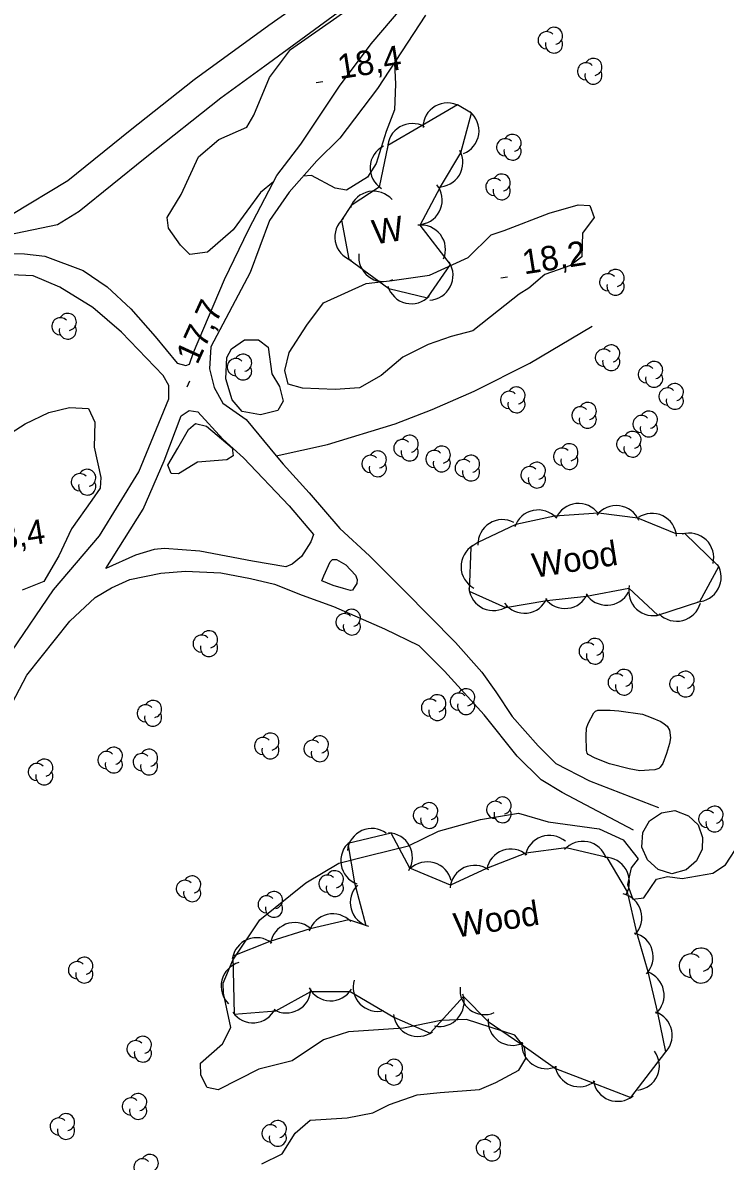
# Model space of a CAD drawing. Extents: x 646142 to 649934, y 5874075 to 5876351.
# Drawn here: x 646701.5 to 646787.3, y 5874932.5 to 5875071.6 of the extents above; entities that cross this region are included whole.
import ezdxf

# ---------------------------------------------------------------- set-up
doc = ezdxf.new("R2010")
doc.units = 0
for name, color, linetype in [('Niveau 2', 7, 'Continuous'), ('Niveau 21', 7, 'Continuous'), ('Niveau 22', 7, 'Continuous'), ('Niveau 3', 7, 'Continuous'), ('Niveau 31', 7, 'Continuous'), ('Niveau 44', 7, 'Continuous')]:
    doc.layers.add(name, color=color, linetype=linetype)

msp = doc.modelspace()

# ---------------------------------------------------------------- linework, layer by layer
at = {"layer": 'Niveau 2'}
for points in [[(646732.14, 5875052.16), (646730.58, 5875050.87), (646727.24, 5875046.31), (646724.1, 5875043.57), (646721.92, 5875043.29), (646720.79, 5875044.42), (646719.34, 5875046.52), (646719.17, 5875047.79), (646720.86, 5875050.6), (646722.97, 5875055.24), (646725.46, 5875057.35), (646728.88, 5875058.83), (646729.74, 5875060.3), (646731.68, 5875064.93), (646734.24, 5875068.32), (646739.89, 5875072.3), (646744.76, 5875075.81), (646746.72, 5875077.72)], [(646746.94, 5875066.77), (646746.91, 5875066.67), (646747.06, 5875064.12), (646746.91, 5875060.96), (646745.91, 5875058.33), (646744.67, 5875054.39), (646743.65, 5875052.74), (646741.06, 5875051.15), (646739.7, 5875051.39), (646736.79, 5875052.92), (646735.79, 5875052.86)], [(646762.17, 5875038.44), (646759.61, 5875036.44), (646756.51, 5875033.94), (646753.84, 5875033.27), (646751.02, 5875032.3), (646747.96, 5875030.73), (646745.3, 5875028.49), (646742.64, 5875027), (646739.7, 5875026.78), (646735.69, 5875026.94), (646733.96, 5875027.44), (646733.54, 5875029.1), (646734.05, 5875031.29), (646736.21, 5875034.66), (646738.25, 5875037.37), (646743.45, 5875039.75), (646746.66, 5875040.11), (646751.19, 5875040.75), (646755.94, 5875042.91), (646758.73, 5875045.69), (646760.31, 5875046.21), (646765.81, 5875048.32), (646769.38, 5875049.35), (646770.78, 5875049.28), (646771.31, 5875047.81), (646769.9, 5875045.9), (646769.79, 5875042.98), (646768.43, 5875041.95), (646765.27, 5875040.83), (646763.32, 5875039.17), (646762.17, 5875038.44)], [(646731.5, 5875031.97), (646731.95, 5875028.69), (646732.89, 5875027.13), (646733.32, 5875025.36), (646732.67, 5875024.2), (646730.56, 5875023.69), (646728.32, 5875024.1), (646727.1, 5875025.52), (646726.31, 5875028.08), (646726.44, 5875030.71), (646727, 5875031.74), (646728.59, 5875032.85), (646730.33, 5875032.87), (646731.5, 5875031.97)], [(646698.5, 5875020.48), (646701.81, 5875022.6), (646704.71, 5875023.99), (646707.22, 5875024.59), (646709.55, 5875024.47), (646710.33, 5875022.79), (646710.23, 5875019.75), (646711.06, 5875016.03), (646710.99, 5875014.74), (646709.95, 5875013.27), (646707.46, 5875009.76), (646705.93, 5875006.44), (646704.1, 5875003.33), (646701.46, 5875002.25)], [(646723.95, 5875022.31), (646727.12, 5875019.65), (646727.21, 5875018.66), (646726.43, 5875018.2), (646722.86, 5875017.92), (646720.54, 5875016.46), (646719.67, 5875016.51), (646719.23, 5875017.53), (646720.46, 5875019.6), (646721.77, 5875021.91), (646722.64, 5875022.62), (646723.95, 5875022.31)], [(646785.81, 5874967.65), (646787.37, 5874968.68), (646789.12, 5874971.38), (646791.44, 5874976.33), (646792.63, 5874983.01), (646794.26, 5874989.25), (646795.31, 5874992.65), (646795.9, 5874994.04), (646796.07, 5874994.05)], [(646761.63, 5874947.87), (646755.72, 5874949.8), (646752.59, 5874949.68), (646748.02, 5874948.74), (646741.32, 5874948.28), (646738.27, 5874947.29), (646734.41, 5874944.72), (646730.37, 5874943.71), (646725.41, 5874941.17), (646724.04, 5874941.47), (646723.28, 5874942.98), (646723.22, 5874944.44), (646725.93, 5874946.8), (646726.93, 5874948.8), (646726.06, 5874952.99), (646726.01, 5874954.21), (646727.18, 5874957.04), (646730.49, 5874961.96), (646736.1, 5874966.48), (646740.14, 5874968.89), (646743.84, 5874969.81), (646748.62, 5874971), (646752.31, 5874972.8), (646757.42, 5874974.24), (646762.06, 5874975), (646765.69, 5874973.94), (646771.91, 5874973.08), (646774.87, 5874971.74), (646776.68, 5874969.43), (646775.85, 5874968.32), (646775.38, 5874966.3), (646776.05, 5874964.49), (646777.37, 5874964.65), (646778.92, 5874966.92), (646780.29, 5874967.26), (646782.06, 5874967), (646785.81, 5874967.65)], [(646730.74, 5874932.13), (646733.2, 5874933.37), (646734.79, 5874935.89), (646736.63, 5874937.49), (646741.14, 5874937.78), (646744.29, 5874938.37), (646746.3, 5874939.4), (646749.68, 5874940.59), (646752.51, 5874940.87), (646757.3, 5874941.24), (646759.32, 5874942.1), (646762.1, 5874943.59), (646762.97, 5874945), (646762.79, 5874946.39), (646761.63, 5874947.87)]]:
    msp.add_lwpolyline(points, dxfattribs=at)
at = {"layer": 'Niveau 21'}
for points in [[(646660.51, 5875034.56), (646667.06, 5875034.01), (646670, 5875033.53), (646672.91, 5875033.52), (646675.53, 5875034.19), (646678.66, 5875035.59), (646684.25, 5875039.75), (646692.46, 5875044.34), (646700.16, 5875048.18), (646707.02, 5875052.32), (646714.63, 5875058.49), (646722.48, 5875064.67), (646731.56, 5875071.3), (646740.22, 5875077.43)], [(646704.21, 5875043.08), (646708.89, 5875041.34), (646711.84, 5875039.35), (646714.73, 5875036.66), (646717.68, 5875033.28), (646720.39, 5875029.99), (646721.45, 5875029.72), (646721.9, 5875029.87), (646722.37, 5875031.31), (646726.16, 5875040.21), (646729.13, 5875046.38), (646732.54, 5875052.92), (646735.47, 5875056.75), (646740.22, 5875063.87), (646744.08, 5875069.05), (646749.05, 5875074.89)], [(646740.49, 5875073.2), (646731.08, 5875066.31), (646725.72, 5875062.41), (646716.46, 5875055.07), (646708.41, 5875048.52), (646705.75, 5875046.92), (646699.71, 5875045.64), (646698.83, 5875044.99), (646698.81, 5875043.83), (646699.31, 5875043.4), (646701.75, 5875043.35), (646704.21, 5875043.08)], [(646750.72, 5875072.52), (646744.84, 5875063.58), (646740.24, 5875057.52), (646737.45, 5875054.75), (646734.06, 5875050.89), (646731.68, 5875047.44), (646729.3, 5875041.09), (646724.48, 5875031.99), (646724.35, 5875029.3), (646724.89, 5875027.02)], [(646700.2, 5874994.82), (646705.27, 5875002.31), (646710.88, 5875008.91), (646715.69, 5875016.73), (646719.37, 5875025.63), (646719.35, 5875027.26), (646718.67, 5875028.49), (646713.58, 5875033.81), (646710.09, 5875036.8), (646706.05, 5875039.29), (646702.8, 5875040.67), (646700.12, 5875040.81)], [(646724.89, 5875027.02), (646725.98, 5875025.12), (646728.81, 5875023.12), (646732.48, 5875018.67), (646733.32, 5875017.65), (646736.51, 5875014.17), (646740.24, 5875009.79), (646743.88, 5875006.46), (646748.06, 5875002.24), (646754.39, 5874995.85), (646757.59, 5874992.25), (646759.3, 5874989.82), (646761.29, 5874986.83), (646764.49, 5874983.23), (646766.64, 5874981.07), (646770.76, 5874978.94), (646778.31, 5874976.02), (646779.19, 5874975.68)], [(646737.05, 5875009.06), (646736.71, 5875008.15), (646735.55, 5875006.38), (646734.44, 5875005.43), (646733.65, 5875005.11), (646729.6, 5875005.79), (646723.17, 5875007.04), (646718.82, 5875007.36), (646717.58, 5875007.22), (646715.28, 5875006.54), (646711.67, 5875004.9), (646716.24, 5875012.15), (646718.78, 5875018.05), (646720.87, 5875023.57), (646721.86, 5875024.22), (646722.92, 5875024.07), (646725.98, 5875020.7), (646728.49, 5875018.44), (646734.08, 5875012.58), (646737.05, 5875009.06), (646737.05, 5875009.06)], [(646739.43, 5875002.83), (646738.06, 5875003.41), (646738.28, 5875004.01), (646739.06, 5875005.74), (646739.37, 5875006.02), (646739.86, 5875006.02), (646741, 5875005.37), (646742.15, 5875004.09), (646742.35, 5875003.58), (646742.31, 5875003.09), (646742.02, 5875002.57), (646741.81, 5875002.26), (646741.57, 5875002.23), (646740.68, 5875002.48), (646739.43, 5875002.83), (646739.43, 5875002.83)], [(646697.9, 5874984.08), (646702.02, 5874991.85), (646707.27, 5874998.48), (646710.35, 5875001.38), (646712.35, 5875002.56), (646714.62, 5875003.58), (646718.37, 5875004.32), (646721.39, 5875004.59), (646725.72, 5875004.37), (646729.33, 5875003.69), (646732.27, 5875002.99), (646735.66, 5875001.65), (646739.49, 5875000.27), (646745.7, 5874997.54), (646749.89, 5874995.51)], [(646776.13, 5874972.94), (646767.39, 5874977.51), (646764.83, 5874979.06), (646761.92, 5874981.98), (646757.9, 5874987.03), (646753.05, 5874992.37), (646749.89, 5874995.51)]]:
    msp.add_lwpolyline(points, dxfattribs=at)
at = {"layer": 'Niveau 22'}
msp.add_lwpolyline([(646732.48, 5875018.67), (646738.75, 5875020.08), (646747.01, 5875022.58), (646751.51, 5875024.32), (646756.66, 5875026.57), (646763.45, 5875030), (646771.08, 5875034.54)], dxfattribs=at)
at = {"layer": 'Niveau 3'}
for p, q in [((646737.37, 5875064.31), (646738.16, 5875064.43)), ((646759.92, 5875040.43), (646760.71, 5875040.55)), ((646721.6, 5875027.11), (646721.93, 5875027.84))]:
    msp.add_line(p, q, dxfattribs=at)
at = {"layer": 'Niveau 31'}
for points in [[(646774.33, 5874987.51), (646777.21, 5874987.09), (646778.27, 5874986.71), (646779.44, 5874986.21), (646779.88, 5874985.94), (646780.23, 5874985.63), (646780.5, 5874985.15), (646780.64, 5874984.22), (646780.52, 5874983.51), (646780.14, 5874982.3), (646779.72, 5874981.07), (646779.37, 5874980.62), (646779.2, 5874980.48), (646778.71, 5874980.31), (646778.03, 5874980.24), (646776.88, 5874980.19), (646775.57, 5874980.42), (646773.18, 5874981.04), (646771.43, 5874981.72), (646770.58, 5874982.19), (646770.47, 5874982.33), (646770.36, 5874982.65), (646770.32, 5874984.47), (646770.37, 5874985.37), (646770.59, 5874985.97), (646771.28, 5874987.28), (646771.46, 5874987.45), (646771.76, 5874987.58), (646772.17, 5874987.57), (646773.28, 5874987.59), (646774.33, 5874987.51), (646774.33, 5874987.51)], [(646777.12, 5874970.85), (646777.25, 5874972.62), (646778.08, 5874974.07), (646779.52, 5874975.05), (646781.18, 5874975.31), (646782.83, 5874974.69), (646784.03, 5874973.58), (646784.54, 5874972.03), (646784.51, 5874970.61), (646783.81, 5874969.19), (646782.55, 5874968.06), (646780.81, 5874967.59), (646779.15, 5874968.13), (646777.83, 5874969.28), (646777.12, 5874970.85)]]:
    msp.add_lwpolyline(points, dxfattribs=at)
at = {"layer": 'Niveau 44'}
for points in [[(646740.47, 5875047.48), (646741.35, 5875042.7), (646746.22, 5875039.12), (646750.94, 5875037.99), (646753.76, 5875042.06), (646750.08, 5875046.88), (646752.54, 5875051.54), (646755.04, 5875055.7), (646756.35, 5875060.55), (646754.62, 5875061.56), (646750.3, 5875059.04), (646746.11, 5875056.59), (646745.07, 5875051.53), (646741.65, 5875049.29), (646740.47, 5875047.48)], [(646781.33, 5875009.16), (646776.65, 5875011.04), (646771.84, 5875011.66), (646766.49, 5875011.29), (646761.74, 5875010.29), (646757.12, 5875008.08), (646756.24, 5875007.53), (646756.06, 5875002.15), (646760.48, 5875000.15), (646765.55, 5875000.99), (646770.37, 5875001.54), (646775.55, 5875002.5), (646779.11, 5874999.2), (646784.23, 5875000.87), (646786.53, 5875005.14), (646782.38, 5875009.18), (646781.33, 5875009.16)], [(646741.36, 5874961.95), (646736.63, 5874960.87), (646731.7, 5874959.32), (646727.19, 5874957.52), (646727.36, 5874950.43), (646732.45, 5874950.86), (646736.7, 5874953.21), (646741.5, 5874953.22), (646746.86, 5874950.07), (646751.3, 5874948.13), (646755.36, 5874952.58), (646758.35, 5874949.55), (646762.34, 5874946.79), (646766.6, 5874943.79), (646771.14, 5874942.05), (646775.81, 5874940.26), (646780.06, 5874945.82), (646779.1, 5874950.58), (646777.9, 5874955.6), (646776.55, 5874960.26), (646775.37, 5874965.39), (646772.92, 5874969.58), (646767.9, 5874970.76), (646762.98, 5874970.13), (646758.17, 5874968.23), (646753.77, 5874966.2), (646748.82, 5874968.29), (646746.52, 5874972.57), (646741.23, 5874971.28), (646742.04, 5874966.5), (646743.44, 5874961.27), (646741.36, 5874961.95)]]:
    msp.add_lwpolyline(points, dxfattribs=at)
for centre, radius, start, end in [((646766.41, 5875070), 1.05, 282.2692, 149.7263), ((646765.51, 5875069.47), 1.05, 44.1154, 269.804), ((646766.41, 5875068.95), 1.05, 166.9369, 29.6212), ((646770.32, 5875065.67), 1.05, 44.1154, 269.804), ((646771.22, 5875066.2), 1.05, 282.2692, 149.7263), ((646771.22, 5875065.15), 1.05, 166.9369, 29.6212), ((646753.41, 5875058.81), 3, 60.3028, 180.2807), ((646754.25, 5875058.41), 3, 291.3813, 51.3592), ((646749.09, 5875056.29), 3, 60.3028, 180.2807), ((646760.45, 5875056.39), 1.05, 44.1154, 269.804), ((646761.35, 5875056.92), 1.05, 282.2692, 149.7263), ((646746.95, 5875053.87), 3, 117.1696, 237.1475), ((646752.28, 5875054.53), 3, 268.8891, 28.867), ((646761.35, 5875055.87), 1.05, 166.9369, 29.6212), ((646760.02, 5875052.07), 1.05, 282.2692, 149.7263), ((646749.76, 5875049.93), 3, 278.8965, 38.8745), ((646759.12, 5875051.54), 1.05, 44.1154, 269.804), ((646760.02, 5875051.02), 1.05, 166.9369, 29.6212), ((646744.37, 5875048.02), 3, 40.9911, 160.969), ((646742.65, 5875045.41), 3, 130.4255, 250.4035), ((646750.16, 5875043.88), 3, 337.5326, 97.5106), ((646745.56, 5875042.98), 3, 172.5528, 292.5308), ((646751.08, 5875040.71), 3, 272.7396, 32.7175), ((646773.03, 5875039.88), 1.05, 44.1154, 269.804), ((646773.93, 5875040.41), 1.05, 282.2692, 149.7263), ((646748.99, 5875040.27), 3, 196.6075, 316.5854), ((646773.93, 5875039.36), 1.05, 166.9369, 29.6212), ((646707.02, 5875035.04), 1.05, 282.2692, 149.7263), ((646706.12, 5875034.51), 1.05, 44.1154, 269.804), ((646707.02, 5875033.99), 1.05, 166.9369, 29.6212), ((646773.4, 5875031.19), 1.05, 282.2692, 149.7263), ((646727.54, 5875029.52), 1.05, 44.1154, 269.804), ((646728.44, 5875030.05), 1.05, 282.2692, 149.7263), ((646772.5, 5875030.66), 1.05, 44.1154, 269.804), ((646773.4, 5875030.14), 1.05, 166.9369, 29.6212), ((646728.44, 5875029), 1.05, 166.9369, 29.6212), ((646777.74, 5875028.63), 1.05, 44.1154, 269.804), ((646778.64, 5875029.16), 1.05, 282.2692, 149.7263), ((646778.64, 5875028.11), 1.05, 166.9369, 29.6212), ((646760.93, 5875025.51), 1.05, 44.1154, 269.804), ((646761.83, 5875026.04), 1.05, 282.2692, 149.7263), ((646780.27, 5875025.93), 1.05, 44.1154, 269.804), ((646781.17, 5875026.46), 1.05, 282.2692, 149.7263), ((646761.83, 5875024.99), 1.05, 166.9369, 29.6212), ((646770.53, 5875024.15), 1.05, 282.2692, 149.7263), ((646781.17, 5875025.41), 1.05, 166.9369, 29.6212), ((646769.63, 5875023.62), 1.05, 44.1154, 269.804), ((646770.53, 5875023.1), 1.05, 166.9369, 29.6212), ((646777.09, 5875022.56), 1.05, 44.1154, 269.804), ((646777.99, 5875023.09), 1.05, 282.2692, 149.7263), ((646777.99, 5875022.04), 1.05, 166.9369, 29.6212), ((646748.78, 5875020.15), 1.05, 282.2692, 149.7263), ((646775.1, 5875020.09), 1.05, 44.1154, 269.804), ((646776, 5875020.62), 1.05, 282.2692, 149.7263), ((646747.88, 5875019.62), 1.05, 44.1154, 269.804), ((646748.78, 5875019.1), 1.05, 166.9369, 29.6212), ((646751.8, 5875018.29), 1.05, 44.1154, 269.804), ((646752.7, 5875018.82), 1.05, 282.2692, 149.7263), ((646767.39, 5875018.58), 1.05, 44.1154, 269.804), ((646768.29, 5875019.11), 1.05, 282.2692, 149.7263), ((646776, 5875019.57), 1.05, 166.9369, 29.6212), ((646743.99, 5875017.69), 1.05, 44.1154, 269.804), ((646744.89, 5875018.22), 1.05, 282.2692, 149.7263), ((646752.7, 5875017.77), 1.05, 166.9369, 29.6212), ((646755.37, 5875017.17), 1.05, 44.1154, 269.804), ((646756.27, 5875017.7), 1.05, 282.2692, 149.7263), ((646768.29, 5875018.06), 1.05, 166.9369, 29.6212), ((646709.4, 5875015.98), 1.05, 282.2692, 149.7263), ((646744.89, 5875017.17), 1.05, 166.9369, 29.6212), ((646756.27, 5875016.65), 1.05, 166.9369, 29.6212), ((646763.42, 5875016.31), 1.05, 44.1154, 269.804), ((646764.32, 5875016.84), 1.05, 282.2692, 149.7263), ((646708.5, 5875015.45), 1.05, 44.1154, 269.804), ((646709.4, 5875014.93), 1.05, 166.9369, 29.6212), ((646764.32, 5875015.79), 1.05, 166.9369, 29.6212), ((646769.4, 5875009.85), 3, 36.0002, 155.9782), ((646774.02, 5875009.6), 3, 22.6794, 142.6573), ((646764.48, 5875009.06), 3, 41.9626, 161.9406), ((646778.38, 5875008.64), 3, 4.1269, 124.1048), ((646760.12, 5875007.88), 3, 62.2016, 182.1795), ((646782.92, 5875006.23), 3, 346.3608, 106.3388), ((646758.05, 5875005.14), 3, 121.1773, 241.1553), ((646783.83, 5875003.84), 3, 271.6434, 31.6213), ((646778.53, 5875002.14), 3, 167.082, 287.0599), ((646759, 5875002.76), 3, 185.6609, 305.6388), ((646762.79, 5875002.44), 3, 216.599, 336.5769), ((646767.76, 5875003.02), 3, 216.599, 336.5769), ((646772.86, 5875003.42), 3, 212.1082, 332.0861), ((646741.72, 5874998.87), 1.05, 282.2692, 149.7263), ((646781.39, 5875001.46), 3, 224.6378, 344.6158), ((646740.82, 5874998.34), 1.05, 44.1154, 269.804), ((646724.27, 5874996.25), 1.05, 282.2692, 149.7263), ((646741.72, 5874997.82), 1.05, 166.9369, 29.6212), ((646723.37, 5874995.72), 1.05, 44.1154, 269.804), ((646724.27, 5874995.2), 1.05, 166.9369, 29.6212), ((646770.51, 5874994.79), 1.05, 44.1154, 269.804), ((646771.41, 5874995.32), 1.05, 282.2692, 149.7263), ((646771.41, 5874994.27), 1.05, 166.9369, 29.6212), ((646774.06, 5874991), 1.05, 44.1154, 269.804), ((646774.96, 5874991.53), 1.05, 282.2692, 149.7263), ((646781.58, 5874990.77), 1.05, 44.1154, 269.804), ((646782.48, 5874991.3), 1.05, 282.2692, 149.7263), ((646755.68, 5874989.16), 1.05, 282.2692, 149.7263), ((646774.96, 5874990.48), 1.05, 166.9369, 29.6212), ((646782.48, 5874990.25), 1.05, 166.9369, 29.6212), ((646717.44, 5874987.73), 1.05, 282.2692, 149.7263), ((646751.26, 5874987.9), 1.05, 44.1154, 269.804), ((646752.16, 5874988.43), 1.05, 282.2692, 149.7263), ((646754.78, 5874988.63), 1.05, 44.1154, 269.804), ((646716.54, 5874987.2), 1.05, 44.1154, 269.804), ((646752.16, 5874987.38), 1.05, 166.9369, 29.6212), ((646755.68, 5874988.11), 1.05, 166.9369, 29.6212), ((646717.44, 5874986.68), 1.05, 166.9369, 29.6212), ((646731.77, 5874983.74), 1.05, 282.2692, 149.7263), ((646730.87, 5874983.21), 1.05, 44.1154, 269.804), ((646731.77, 5874982.69), 1.05, 166.9369, 29.6212), ((646736.91, 5874982.86), 1.05, 44.1154, 269.804), ((646737.81, 5874983.39), 1.05, 282.2692, 149.7263), ((646711.75, 5874981.49), 1.05, 44.1154, 269.804), ((646712.65, 5874982.02), 1.05, 282.2692, 149.7263), ((646716.05, 5874981.24), 1.05, 44.1154, 269.804), ((646716.95, 5874981.77), 1.05, 282.2692, 149.7263), ((646737.81, 5874982.34), 1.05, 166.9369, 29.6212), ((646703.25, 5874980.03), 1.05, 44.1154, 269.804), ((646704.15, 5874980.56), 1.05, 282.2692, 149.7263), ((646712.65, 5874980.97), 1.05, 166.9369, 29.6212), ((646716.95, 5874980.72), 1.05, 166.9369, 29.6212), ((646704.15, 5874979.51), 1.05, 166.9369, 29.6212), ((646751.17, 5874975.24), 1.05, 282.2692, 149.7263), ((646759.23, 5874975.4), 1.05, 44.1154, 269.804), ((646760.13, 5874975.93), 1.05, 282.2692, 149.7263), ((646750.27, 5874974.71), 1.05, 44.1154, 269.804), ((646760.13, 5874974.88), 1.05, 166.9369, 29.6212), ((646785.12, 5874974.28), 1.05, 44.1154, 269.804), ((646786.02, 5874974.81), 1.05, 282.2692, 149.7263), ((646751.17, 5874974.19), 1.05, 166.9369, 29.6212), ((646786.02, 5874973.76), 1.05, 166.9369, 29.6212), ((646744.16, 5874970.13), 3, 53.8414, 173.8194), ((646746.12, 5874969.59), 3, 328.3065, 88.2844), ((646765.85, 5874969.28), 3, 49.5743, 169.5522), ((646743.37, 5874969.18), 3, 129.5826, 249.5606), ((646769.94, 5874968.56), 3, 18.7085, 138.6864), ((646761.14, 5874967.61), 3, 49.5743, 169.5522), ((646772.63, 5874966.59), 3, 330.3576, 90.3355), ((646739.64, 5874966.92), 1.05, 282.2692, 149.7263), ((646750.93, 5874966.05), 3, 13.7176, 133.6955), ((646756.71, 5874965.62), 3, 54.822, 174.8), ((646721.32, 5874965.75), 1.05, 44.1154, 269.804), ((646722.22, 5874966.28), 1.05, 282.2692, 149.7263), ((646738.74, 5874966.39), 1.05, 44.1154, 269.804), ((646722.22, 5874965.23), 1.05, 166.9369, 29.6212), ((646732.21, 5874964.38), 1.05, 282.2692, 149.7263), ((646739.64, 5874965.87), 1.05, 166.9369, 29.6212), ((646744.53, 5874964.07), 3, 134.6204, 254.5983), ((646774.14, 5874962.24), 3, 316.1861, 76.1641), ((646731.31, 5874963.85), 1.05, 44.1154, 269.804), ((646732.21, 5874963.33), 1.05, 166.9369, 29.6212), ((646739.39, 5874959.7), 3, 42.8611, 162.8391), ((646734.74, 5874958.63), 3, 51.6943, 171.6722), ((646730.09, 5874956.78), 3, 51.6943, 171.6722), ((646775.53, 5874957.44), 3, 316.1861, 76.1641), ((646784.36, 5874957.09), 1.42, 282.2692, 149.7262), ((646708.14, 5874955.81), 1.05, 44.1154, 269.804), ((646709.04, 5874956.34), 1.05, 282.2692, 149.7263), ((646728.75, 5874953.86), 3, 105.8876, 225.8656), ((646783.13, 5874956.37), 1.42, 44.1153, 269.8039), ((646709.04, 5874955.29), 1.05, 166.9369, 29.6212), ((646776.86, 5874952.75), 3, 311.4181, 71.396), ((646784.36, 5874955.66), 1.42, 166.9368, 29.6212), ((646744.87, 5874953.78), 3, 164.0703, 284.0483), ((646733.72, 5874953.58), 3, 238.909, 358.8869), ((646739.14, 5874955.07), 3, 207.9554, 327.9333), ((646752.43, 5874951.93), 3, 258.4222, 18.4002), ((646757.93, 5874953.38), 3, 173.1938, 293.1718), ((646729.64, 5874952.38), 3, 214.4357, 334.4136), ((646749.79, 5874950.71), 3, 186.4291, 306.407), ((646761.35, 5874949.62), 3, 175.2736, 295.2515), ((646777.85, 5874947.85), 3, 311.4181, 71.396), ((646715.3, 5874946.15), 1.05, 44.1154, 269.804), ((646716.2, 5874946.68), 1.05, 282.2692, 149.7263), ((646765.46, 5874946.77), 3, 175.2736, 295.2515), ((646716.2, 5874945.63), 1.05, 166.9369, 29.6212), ((646776.28, 5874944.12), 3, 276.7016, 36.6795), ((646745.96, 5874943.34), 1.05, 44.1154, 269.804), ((646746.86, 5874943.87), 1.05, 282.2692, 149.7263), ((646746.86, 5874942.82), 1.05, 166.9369, 29.6212), ((646769.5, 5874944.57), 3, 189.0603, 309.0383), ((646774.17, 5874942.78), 3, 189.0603, 309.0383), ((646714.72, 5874939.15), 1.05, 44.1154, 269.804), ((646715.62, 5874939.68), 1.05, 282.2692, 149.7263), ((646715.62, 5874938.63), 1.05, 166.9369, 29.6212), ((646705.91, 5874936.7), 1.05, 44.1154, 269.804), ((646706.81, 5874937.23), 1.05, 282.2692, 149.7263), ((646732.68, 5874936.39), 1.05, 282.2692, 149.7263), ((646706.81, 5874936.18), 1.05, 166.9369, 29.6212), ((646731.78, 5874935.86), 1.05, 44.1154, 269.804), ((646732.68, 5874935.34), 1.05, 166.9369, 29.6212), ((646757.94, 5874934.06), 1.05, 44.1154, 269.804), ((646758.84, 5874934.59), 1.05, 282.2692, 149.7263), ((646717.04, 5874932.24), 1.05, 282.2692, 149.7263), ((646758.84, 5874933.54), 1.05, 166.9369, 29.6212), ((646716.14, 5874931.71), 1.05, 44.1154, 269.804)]:
    msp.add_arc(centre, radius, start, end, dxfattribs=at)

# ---------------------------------------------------------------- texts
at = {"layer": 'Niveau 3'}
for s, rotation, p in [('18,4 ', 8.9405, (646740.22, 5875064.71)), ('18,2 ', 8.9405, (646762.77, 5875040.84)), ('17,7 ', 65.416, (646722.84, 5875029.71)), ('18,4 ', 8.9405, (646696.71, 5875006.81))]:
    msp.add_text(s, height=3, rotation=rotation, dxfattribs=at).set_placement(p)
at = {"layer": 'Niveau 44'}
for s, p in [('W', (646744.45, 5875044.49)), ('Wood', (646764, 5875003.75)), ('Wood', (646754.42, 5874959.77))]:
    msp.add_text(s, height=3, rotation=8.9405, dxfattribs=at).set_placement(p)

doc.saveas('drawing.dxf')
